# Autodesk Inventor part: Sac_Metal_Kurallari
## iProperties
Shininess: 3
Length Units: 11272
Angle Units: 11279
Time Units: 11290
Mass Units: 11286
Length Display Precision: 3
Angle Display Precision: 2
Compacted: True
Created: 2001-08
Part Number: Sac_Metal_Kurallari
Material: Steel, Mild
Document SubType Name: Sheet Metal
Designer: jahraul
Density: 7.86 g/cm^3
Flat Pattern Width: 18.5216 cm
Flat Pattern Length: 25.9005 cm
Flat Pattern Area: 479.718 cm^2
Sheet Metal Rule: Steel 16 Ga
Density: 0.0
Volumn: 0.0
Area: 0.0
PropertySet Name: Model Information
Control State: 0
Master: False
Checked Out: False
Author: jahraul
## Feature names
1. Corner1
2. Corner2
3. Corner3
4. Corner4
5. Corner Chamfer1
6. Hole1
7. Plate1
8. Bend1
9. Plate2
10. Bend2
11. Plate3
12. Bend3
13. Plate4
14. Bend4
15. Plate5
16. Bend5
17. Cut1
18. Cut2
19. Cut3
